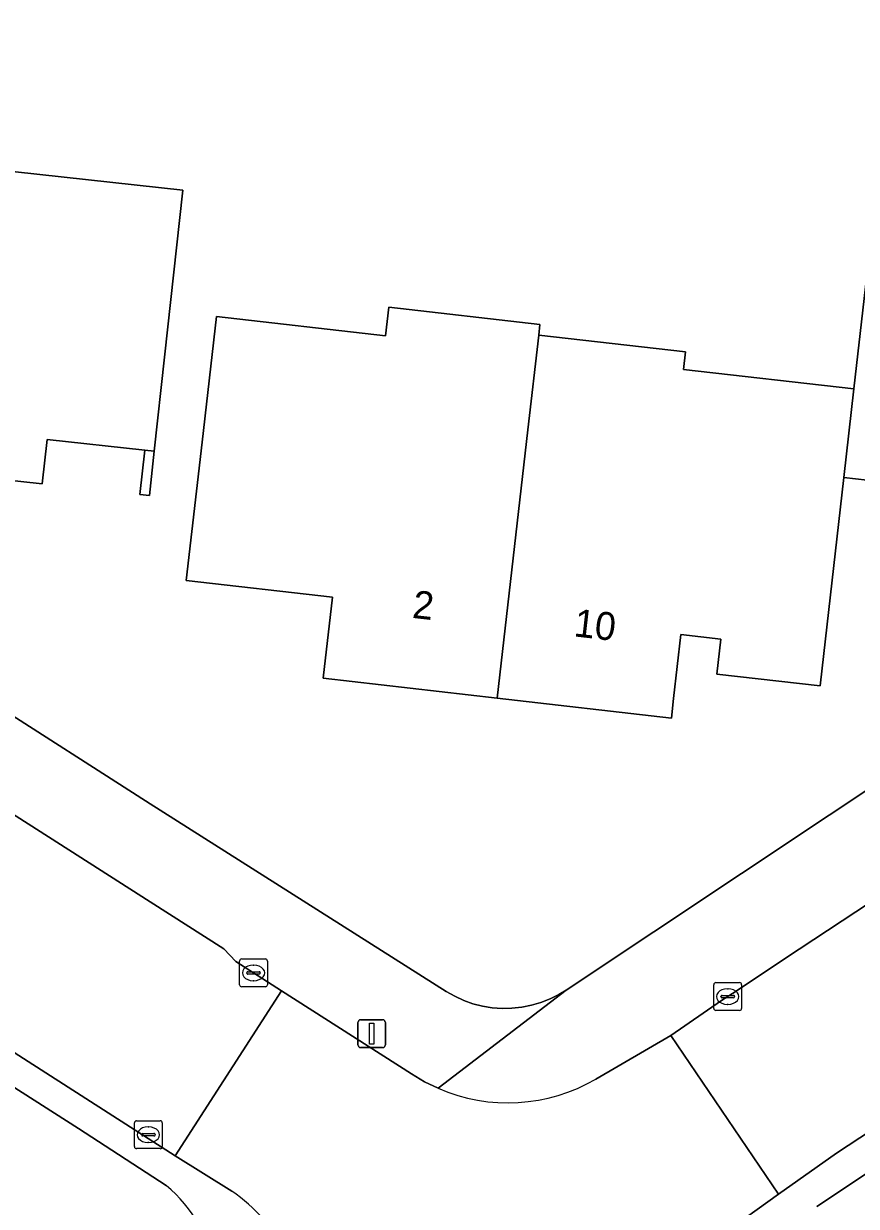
# Model space of a CAD drawing. Extents: x 162396 to 163643, y 386452 to 387406.
# Drawn here: x 162995.45 to 163025.37, y 386731.76 to 386774.24 of the extents above; entities that cross this region are included whole.
import ezdxf

# ---------------------------------------------------------------- set-up
doc = ezdxf.new("R2010")
doc.units = 0
for name, color, linetype in [('IMGEO_Erf', 7, 'Continuous'), ('IMGEO_Groenvoorziening', 7, 'Continuous'), ('IMGEO_Kolk', 7, 'Continuous'), ('IMGEO_Lichtmast', 7, 'Continuous'), ('IMGEO_Muur', 7, 'Continuous'), ('IMGEO_Pand', 7, 'Continuous'), ('IMGEO_Pand_nummerreeks', 7, 'Continuous'), ('IMGEO_Rijbaan_lokaal_gesloten', 7, 'Continuous'), ('IMGEO_Rijbaan_lokaal_open', 7, 'Continuous'), ('IMGEO_Voetpad_open', 7, 'Continuous')]:
    doc.layers.add(name, color=color, linetype=linetype)

msp = doc.modelspace()

# ---------------------------------------------------------------- linework, layer by layer
at = {"layer": 'IMGEO_Erf'}
for points in [[(162983.26, 386826.659), (162939.497, 386855.132), (162935.841, 386824.556), (162935.369, 386820.614), (162931.696, 386789.898), (162994.075, 386750), (163000, 386746.21), (163010.632, 386739.479), (163010.94, 386739.303), (163011.262, 386739.156), (163011.596, 386739.037), (163011.94, 386738.949), (163012.29, 386738.893), (163012.643, 386738.867), (163012.998, 386738.873), (163013.35, 386738.911), (163013.698, 386738.981), (163014.038, 386739.081), (163014.368, 386739.211), (163014.685, 386739.37), (163014.944, 386739.528), (163030.691, 386750), (163094.938, 386792.726)], [(163028.276, 386757.554), (163024.923, 386757.937), (163024.067, 386750.448), (163020.358, 386750.871), (163020.501, 386752.127), (163019.068, 386752.291), (163018.806, 386750), (163018.725, 386749.294), (163012.47, 386750.008), (163006.213, 386750.723), (163006.545, 386753.632), (163001.291, 386754.232), (163001.859, 386759.2), (163002.375, 386763.72), (163008.45, 386763.025), (163008.567, 386764.05), (163014.004, 386763.429), (163013.961, 386763.046), (163019.238, 386762.443), (163019.166, 386761.814), (163025.28, 386761.115), (163026.716, 386773.684)], [(163053.391, 386751.338), (163051.379, 386750), (163043.727, 386744.911), (163023.952, 386731.758)]]:
    msp.add_lwpolyline(points, dxfattribs=at)
msp.add_lwpolyline([(162991.643, 386769.298), (163001.165, 386768.261), (163000.511, 386762.256), (163000.143, 386758.876), (162999.97, 386757.285), (162999.629, 386757.322), (162999.802, 386758.913), (162996.29, 386759.295), (162996.117, 386757.706), (162990.082, 386758.363), (162990.329, 386760.633), (162984.498, 386761.268), (162984.663, 386762.791), (162980.931, 386763.198), (162981.312, 386766.698), (162981.956, 386772.611), (162991.886, 386771.529)], close=True, dxfattribs=at)
at = {"layer": 'IMGEO_Groenvoorziening'}
msp.add_lwpolyline([(163000.576, 386732.506), (162997.421, 386734.557), (162965.791, 386754.754)], dxfattribs=at)
msp.add_arc((162997.074, 386728.355), 5.431, 333.4662, 49.8498, dxfattribs=at)
at = {"layer": 'IMGEO_Kolk'}
for p, q in [((163003.21, 386739.717), (163003.21, 386740.569)), ((163003.285, 386740.643), (163004.137, 386740.643)), ((163004.211, 386740.569), (163004.211, 386739.717)), ((163003.469, 386740.137), (163003.469, 386740.149)), ((163003.512, 386740.186), (163003.91, 386740.186)), ((163003.698, 386740.423), (163003.723, 386740.423)), ((163003.953, 386740.149), (163003.953, 386740.137)), ((163003.907, 386740.1), (163003.509, 386740.1)), ((163003.721, 386739.863), (163003.696, 386739.863)), ((163020.249, 386738.867), (163020.249, 386739.719)), ((163020.324, 386739.793), (163021.176, 386739.793)), ((163021.25, 386739.719), (163021.25, 386738.867)), ((163004.137, 386739.643), (163003.285, 386739.643)), ((163020.508, 386739.287), (163020.508, 386739.299)), ((163020.551, 386739.336), (163020.949, 386739.336)), ((163020.737, 386739.573), (163020.762, 386739.573)), ((163020.992, 386739.299), (163020.992, 386739.287)), ((163020.946, 386739.25), (163020.548, 386739.25)), ((163020.76, 386739.013), (163020.735, 386739.013)), ((163021.176, 386738.793), (163020.324, 386738.793)), ((162999.431, 386733.904), (162999.431, 386734.756)), ((162999.506, 386734.83), (163000.358, 386734.83)), ((163000.432, 386734.756), (163000.432, 386733.904)), ((162999.69, 386734.324), (162999.69, 386734.336)), ((163000.128, 386734.287), (162999.73, 386734.287)), ((162999.733, 386734.373), (163000.131, 386734.373)), ((162999.919, 386734.61), (162999.944, 386734.61)), ((163000.174, 386734.336), (163000.174, 386734.324)), ((163000.358, 386733.83), (162999.506, 386733.83)), ((162999.942, 386734.05), (162999.917, 386734.05))]:
    msp.add_line(p, q, dxfattribs=at)
for points in [[(163003.21, 386739.717), (163003.21, 386740.569)], [(163003.285, 386740.643), (163004.137, 386740.643)], [(163004.211, 386740.569), (163004.211, 386739.717)], [(163020.249, 386738.867), (163020.249, 386739.719)], [(163020.324, 386739.793), (163021.176, 386739.793)], [(163021.25, 386739.719), (163021.25, 386738.867)], [(163004.137, 386739.643), (163003.285, 386739.643)], [(163021.176, 386738.793), (163020.324, 386738.793)], [(162999.431, 386733.904), (162999.431, 386734.756)], [(162999.506, 386734.83), (163000.358, 386734.83)], [(163000.432, 386734.756), (163000.432, 386733.904)], [(163000.358, 386733.83), (162999.506, 386733.83)]]:
    msp.add_lwpolyline(points, dxfattribs=at)
for centre, radius, start, end in [((163003.287, 386740.567), 0.0765, 91.552, 178.448), ((163003.287, 386740.567), 0.0765, 91.552, 178.448), ((163004.135, 386740.567), 0.0765, 1.552, 88.448), ((163004.135, 386740.567), 0.0765, 1.552, 88.448), ((163003.509, 386740.146), 0.0403, 85.8775, 175.7526), ((163003.506, 386740.136), 0.0366, 178.938, 274.7102), ((163003.91, 386740.143), 0.043, 264.8664, 352.4533), ((163003.914, 386740.148), 0.0386, 1.7309, 96.639), ((163003.287, 386739.719), 0.0765, 181.552, 268.448), ((163003.287, 386739.719), 0.0765, 181.552, 268.448), ((163004.135, 386739.719), 0.0765, 271.552, 358.448), ((163004.135, 386739.719), 0.0765, 271.552, 358.448), ((163020.326, 386739.717), 0.0765, 91.552, 178.448), ((163020.326, 386739.717), 0.0765, 91.552, 178.448), ((163021.174, 386739.717), 0.0765, 1.552, 88.448), ((163021.174, 386739.717), 0.0765, 1.552, 88.448), ((163020.548, 386739.296), 0.0403, 85.8775, 175.7526), ((163020.545, 386739.286), 0.0366, 178.938, 274.7102), ((163020.949, 386739.293), 0.043, 264.8664, 352.4533), ((163020.953, 386739.298), 0.0386, 1.7309, 96.639), ((163020.326, 386738.869), 0.0765, 181.552, 268.448), ((163020.326, 386738.869), 0.0765, 181.552, 268.448), ((163021.174, 386738.869), 0.0765, 271.552, 358.448), ((163021.174, 386738.869), 0.0765, 271.552, 358.448), ((162999.508, 386734.754), 0.0765, 91.552, 178.448), ((162999.508, 386734.754), 0.0765, 91.552, 178.448), ((163000.356, 386734.754), 0.0765, 1.552, 88.448), ((163000.356, 386734.754), 0.0765, 1.552, 88.448), ((162999.73, 386734.333), 0.0403, 85.8775, 175.7526), ((162999.727, 386734.323), 0.0366, 178.938, 274.7102), ((163000.131, 386734.33), 0.043, 264.8664, 352.4533), ((163000.135, 386734.335), 0.0386, 1.7309, 96.639), ((162999.508, 386733.906), 0.0765, 181.552, 268.448), ((162999.508, 386733.906), 0.0765, 181.552, 268.448), ((163000.356, 386733.906), 0.0765, 271.552, 358.448), ((163000.356, 386733.906), 0.0765, 271.552, 358.448)]:
    msp.add_arc(centre, radius, start, end, dxfattribs=at)
for centre, major_axis, ratio, start_param, end_param in [((163003.697, 386740.143), (-0.387, 0.002), 0.722429, 4.712389, 7.853982), ((163003.722, 386740.143), (-0.39, 0.002), 0.717154, 1.570796, 4.712389), ((163020.736, 386739.293), (-0.387, 0.002), 0.722429, 4.712389, 7.853982), ((163020.761, 386739.293), (-0.39, 0.002), 0.717154, 1.570796, 4.712389), ((162999.918, 386734.33), (-0.387, 0.002), 0.722429, 4.712389, 7.853982), ((162999.943, 386734.33), (-0.39, 0.002), 0.717154, 1.570796, 4.712389)]:
    msp.add_ellipse(centre, major_axis=major_axis, ratio=ratio, start_param=start_param, end_param=end_param, dxfattribs=at)
at = {"layer": 'IMGEO_Lichtmast'}
for p, q in [((163007.559, 386738.46), (163008.349, 386738.46)), ((163008.349, 386738.46), (163007.559, 386738.46)), ((163007.459, 386737.56), (163007.459, 386738.36)), ((163007.459, 386738.36), (163007.459, 386737.56)), ((163008.449, 386738.36), (163008.449, 386737.56)), ((163008.449, 386737.56), (163008.449, 386738.36)), ((163008.349, 386737.46), (163007.559, 386737.46)), ((163007.559, 386737.46), (163008.349, 386737.46))]:
    msp.add_line(p, q, dxfattribs=at)
msp.add_lwpolyline([(163007.879, 386738.335), (163008.029, 386738.335), (163008.029, 386737.585), (163007.879, 386737.585), (163007.879, 386738.335)], dxfattribs=at)
for centre, start, end in [((163007.559, 386738.36), 90, 180), ((163007.559, 386738.36), 90, 180), ((163008.349, 386738.36), 0, 90), ((163008.349, 386738.36), 360, 90), ((163007.559, 386737.56), 180, 270), ((163007.559, 386737.56), 180, 270), ((163008.349, 386737.56), 270, 0), ((163008.349, 386737.56), 270, 0)]:
    msp.add_arc(centre, 0.1, start, end, dxfattribs=at)
at = {"layer": 'IMGEO_Muur'}
msp.add_lwpolyline([(163000.143, 386758.876), (162999.802, 386758.913), (162999.629, 386757.322), (162999.97, 386757.285)], close=True, dxfattribs=at)
at = {"layer": 'IMGEO_Pand'}
for points in [[(163038.409, 386773.163), (163035.259, 386773.523), (163030.074, 386774.115), (163029.982, 386773.311), (163026.716, 386773.684), (163025.28, 386761.115), (163024.923, 386757.937), (163028.276, 386757.554), (163029.133, 386765.055), (163037.378, 386764.113), (163037.541, 386765.536)], [(163001.165, 386768.261), (162991.643, 386769.298), (162991.46, 386769.317), (162990.512, 386760.613), (162990.329, 386760.633), (162990.082, 386758.363), (162996.117, 386757.706), (162996.29, 386759.295), (162999.802, 386758.913), (163000.143, 386758.876), (163000.511, 386762.256)], [(163002.375, 386763.72), (163001.859, 386759.2), (163001.291, 386754.232), (163006.545, 386753.632), (163006.213, 386750.723), (163012.47, 386750.008), (163013.572, 386759.652), (163013.961, 386763.046), (163014.004, 386763.429), (163008.567, 386764.05), (163008.45, 386763.025)], [(163019.166, 386761.814), (163019.238, 386762.443), (163013.961, 386763.046), (163013.572, 386759.652), (163012.47, 386750.008), (163018.725, 386749.294), (163018.806, 386750), (163019.068, 386752.291), (163020.501, 386752.127), (163020.358, 386750.871), (163024.067, 386750.448), (163024.923, 386757.937), (163025.28, 386761.115)]]:
    msp.add_lwpolyline(points, close=True, dxfattribs=at)
at = {"layer": 'IMGEO_Rijbaan_lokaal_gesloten'}
for points in [[(163065.539, 386760.542), (163085.934, 386774.259), (163087.891, 386775.462), (163086.931, 386776.836), (163084.887, 386779.893), (163084.016, 386781.282), (163053.527, 386761.018), (163044.946, 386755.247), (163037.12, 386750.107), (163027.385, 386743.673), (163022.823, 386740.671), (163021.049, 386739.492), (163020.532, 386739.148), (163018.704, 386737.897), (163022.574, 386732.192), (163024.659, 386733.665), (163043.288, 386745.904), (163047.031, 386748.398), (163049.437, 386750), (163051.556, 386751.416), (163051.609, 386751.451), (163051.663, 386751.486)], [(162976.584, 386757.684), (162972.881, 386760.057), (162961.015, 386767.66), (162957.257, 386770.068), (162955.683, 386771.076), (162951.851, 386773.532), (162947.417, 386776.185), (162944.171, 386778.263), (162940.349, 386772.312), (162975.708, 386749.721), (163000.894, 386733.571), (163004.712, 386739.504), (163003.079, 386740.546), (163002.637, 386741.003), (163000, 386742.69), (162994.876, 386745.969), (162988.576, 386750), (162982.93, 386753.617), (162979.258, 386755.97)]]:
    msp.add_lwpolyline(points, close=True, dxfattribs=at)
at = {"layer": 'IMGEO_Rijbaan_lokaal_open'}
for points in [[(163010.346, 386735.997), (163009.856, 386736.236), (163009.389, 386736.517), (163004.712, 386739.504), (163000.894, 386733.571), (163002.93, 386732.299)], [(163020.571, 386730.756), (163022.574, 386732.192), (163018.704, 386737.897), (163016.013, 386736.331)]]:
    msp.add_lwpolyline(points, dxfattribs=at)
for centre, radius, start, end in [((163012.851, 386741.743), 6.268, 246.4489, 300.2971), ((162999.698, 386727.524), 5.766, 25.8067, 55.9064)]:
    msp.add_arc(centre, radius, start, end, dxfattribs=at)
at = {"layer": 'IMGEO_Voetpad_open'}
for points in [[(163090.874, 386798.95), (163094.938, 386792.726), (163030.691, 386750), (163014.944, 386739.528), (163010.346, 386735.997)], [(163016.013, 386736.331), (163018.704, 386737.897), (163020.532, 386739.148), (163021.049, 386739.492), (163022.823, 386740.671), (163027.385, 386743.673), (163037.12, 386750.107), (163044.946, 386755.247), (163053.527, 386761.018), (163084.016, 386781.282)], [(162936.369, 386773.302), (162937.555, 386772.892), (162965.791, 386754.754), (162997.421, 386734.557), (163000.576, 386732.506)], [(163002.93, 386732.299), (163000.894, 386733.571), (162975.708, 386749.721), (162940.349, 386772.312), (162938.559, 386773.627)], [(163051.663, 386751.486), (163051.609, 386751.451), (163051.556, 386751.416), (163049.437, 386750), (163047.031, 386748.398), (163043.288, 386745.904), (163024.659, 386733.665), (163022.574, 386732.192), (163020.571, 386730.756)], [(162994.876, 386745.969), (163000, 386742.69), (163002.637, 386741.003), (163003.079, 386740.546), (163004.712, 386739.504), (163009.389, 386736.517), (163009.856, 386736.236), (163010.346, 386735.997), (163014.944, 386739.528), (163014.685, 386739.37), (163014.368, 386739.211), (163014.038, 386739.081), (163013.698, 386738.981), (163013.35, 386738.911), (163012.998, 386738.873), (163012.643, 386738.867), (163012.29, 386738.893), (163011.94, 386738.949), (163011.596, 386739.037), (163011.262, 386739.156), (163010.94, 386739.303), (163010.632, 386739.479), (163000, 386746.21), (162994.075, 386750)], [(163023.952, 386731.758), (163043.727, 386744.911)]]:
    msp.add_lwpolyline(points, dxfattribs=at)
for centre, radius, start, end in [((163012.851, 386741.743), 6.268, 246.4489, 300.2971), ((162997.074, 386728.355), 5.431, 333.4662, 49.8498), ((162999.698, 386727.524), 5.766, 25.8067, 55.9064)]:
    msp.add_arc(centre, radius, start, end, dxfattribs=at)

# ---------------------------------------------------------------- texts
at = {"layer": 'IMGEO_Pand_nummerreeks'}
for s, rotation, p in [('2', 353.484, (163009.388, 386752.897)), ('10', 353.4849, (163015.192, 386752.233))]:
    msp.add_text(s, height=1, rotation=rotation, dxfattribs=at).set_placement(p)

doc.saveas('drawing.dxf')
